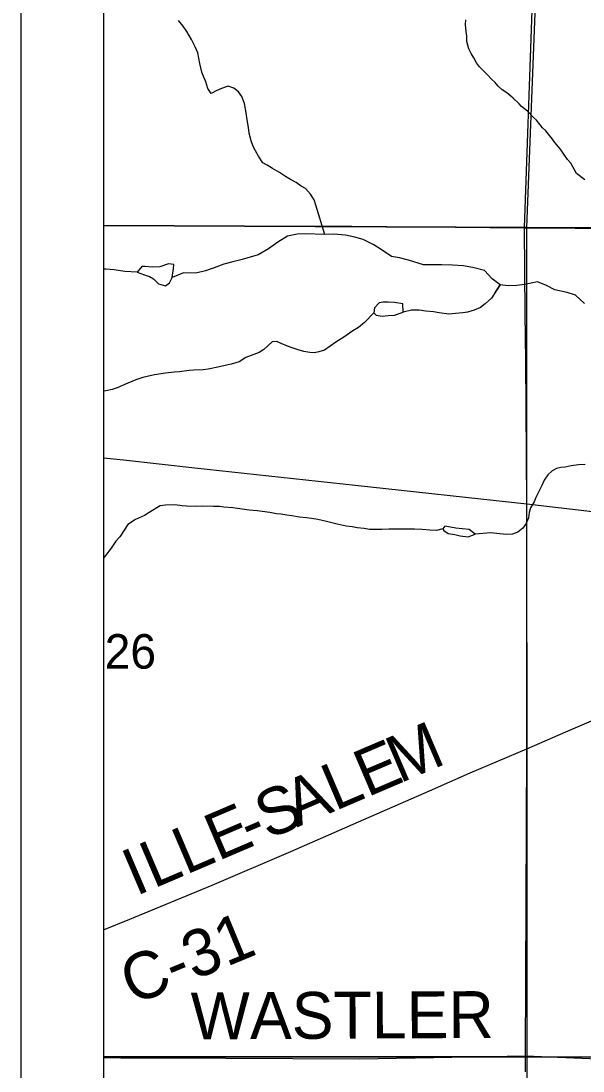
# Model space of a CAD drawing. Extents: x -209 to 4852, y 0 to 905.
# Drawn here: x 252.83 to 266.46, y 258.31 to 283.76 of the extents above; entities that cross this region are included whole.
import ezdxf

# ---------------------------------------------------------------- set-up
doc = ezdxf.new("R2010")
doc.units = 0
for name, color, linetype in [('Default', 7, 'Continuous'), ('GM_P_County_Alignment', 7, 'Continuous'), ('GM_X_County_Road', 7, 'Continuous'), ('GM_X_County_Road_Text', 7, 'Continuous'), ('GM_X_County_ROW', 7, 'Continuous'), ('GM_X_Major_River', 7, 'Continuous'), ('GM_X_Minor_Lake_Text', 7, 'Continuous'), ('GM_X_Minor_River', 7, 'Continuous'), ('GM_X_Rail_Line_Text', 7, 'Continuous'), ('GM_X_Township_Road', 7, 'Continuous'), ('GM_X_Township_Road_Text', 7, 'Continuous'), ('SH_Data', 7, 'Continuous')]:
    doc.layers.add(name, color=color, linetype=linetype)

msp = doc.modelspace()

# ---------------------------------------------------------------- linework, layer by layer
at = {"layer": 'Default'}
msp.add_lwpolyline([(390.832, 338.559), (254.832, 338.559), (254.832, 202.559), (390.832, 202.559)], close=True, dxfattribs=at)
at = {"layer": 'GM_X_County_Road'}
for points in [[(266.5, 279.912), (266.299, 280.069), (266.161, 280.315), (266.08, 280.408), (265.904, 280.663), (265.772, 280.818), (265.713, 280.903), (265.551, 281.104), (265.477, 281.174), (265.33, 281.36), (265.255, 281.423), (265.107, 281.578), (264.966, 281.695), (264.907, 281.758), (264.766, 281.898), (264.707, 281.945), (264.61, 282.023), (264.498, 282.094), (264.402, 282.187), (264.328, 282.273), (264.239, 282.358), (264.135, 282.467), (264.032, 282.568), (263.95, 282.654), (263.877, 282.754), (263.811, 282.87), (263.746, 282.978), (263.688, 283.093), (263.639, 283.269), (263.642, 283.398), (263.622, 283.512), (263.611, 283.679), (263.614, 283.793)], [(260.195, 278.593), (259.976, 279.298), (259.941, 279.428), (259.854, 279.567), (259.728, 279.706), (259.623, 279.762), (259.504, 279.849), (259.362, 279.92), (259.242, 279.992), (259.101, 280.094), (258.928, 280.189), (258.801, 280.268), (258.697, 280.331), (258.587, 280.486), (258.514, 280.617), (258.464, 280.724), (258.414, 280.862), (258.365, 281.046), (258.346, 281.183), (258.312, 281.373), (258.294, 281.541), (258.254, 281.769), (258.182, 281.931), (258.101, 282.046), (257.99, 282.14), (257.854, 282.189), (257.694, 282.132), (257.563, 282.075), (257.44, 282.01), (257.36, 282.125), (257.311, 282.294), (257.268, 282.401), (257.218, 282.524), (257.17, 282.737), (257.116, 282.997), (257.058, 283.142), (256.964, 283.319), (256.855, 283.512), (256.76, 283.643), (256.649, 283.775)], [(266.488, 276.919), (266.273, 277.123), (266.069, 277.183), (265.773, 277.245), (265.571, 277.35), (265.352, 277.44), (265.045, 277.381), (264.854, 277.356), (264.64, 277.348), (264.45, 277.369), (264.257, 277.519), (264.064, 277.715), (263.815, 277.783), (263.557, 277.829), (263.291, 277.845), (263.032, 277.853), (262.803, 277.852), (262.59, 277.858), (262.227, 277.968), (262.007, 278.021), (261.81, 278.057), (261.586, 278.208), (261.384, 278.336), (261.129, 278.465), (260.925, 278.525), (260.697, 278.57), (260.416, 278.594), (260.195, 278.593), (259.723, 278.607), (259.524, 278.598), (259.294, 278.551), (259.061, 278.406), (258.835, 278.246), (258.578, 278.094), (258.194, 277.984), (257.971, 277.93), (257.748, 277.868), (257.517, 277.784), (257.301, 277.707)], [(255.649, 277.674), (255.348, 277.697), (255.09, 277.736), (254.892, 277.749), (254.832, 277.749)], [(257.301, 277.707), (257.07, 277.653), (256.773, 277.662), (256.498, 277.55)], [(264.321, 277.166), (264.45, 277.369), (264.238, 277.045), (264.083, 276.912), (263.967, 276.824), (263.821, 276.752), (263.653, 276.71), (263.546, 276.69), (263.364, 276.672), (263.204, 276.661), (262.97, 276.689), (262.834, 276.715), (262.644, 276.728), (262.486, 276.754), (262.296, 276.759), (262.099, 276.707)], [(261.384, 276.692), (261.159, 276.46), (261.011, 276.335), (260.88, 276.255), (260.657, 276.101), (260.464, 275.977), (260.186, 275.786), (260.056, 275.744), (259.949, 275.724), (259.836, 275.726), (259.692, 275.753), (259.549, 275.794), (259.406, 275.843), (259.293, 275.884), (259.136, 275.949), (259.031, 275.997), (258.917, 275.992), (258.715, 275.8), (258.607, 275.726), (258.408, 275.655), (258.285, 275.605), (258.123, 275.503), (257.925, 275.447), (257.604, 275.371), (257.368, 275.324), (257.246, 275.312), (257.018, 275.302), (256.912, 275.29), (256.676, 275.265), (256.554, 275.253), (256.334, 275.228), (256.067, 275.189), (255.892, 275.148), (255.785, 275.12), (255.617, 275.071), (255.425, 274.985), (255.295, 274.927), (255.164, 274.877), (255.042, 274.835), (254.889, 274.801), (254.832, 274.789)], [(266.506, 273.012), (266.347, 273.008), (266.172, 272.982), (266.027, 272.948), (265.92, 272.943), (265.813, 272.915), (265.706, 272.865), (265.605, 272.761), (265.518, 272.634), (265.454, 272.506), (265.374, 272.341), (265.311, 272.214), (265.27, 272.109), (265.183, 271.967), (265.15, 271.853), (265.132, 271.725), (265.075, 271.582), (264.997, 271.47), (264.873, 271.375), (264.743, 271.325), (264.598, 271.321), (264.439, 271.332), (264.22, 271.36), (263.843, 271.327)], [(263.055, 271.458), (262.901, 271.415), (262.742, 271.427), (262.553, 271.439), (262.371, 271.451), (262.181, 271.448), (262.022, 271.445), (261.749, 271.444), (261.582, 271.44), (261.453, 271.443), (261.278, 271.44), (261.15, 271.466), (260.984, 271.478), (260.863, 271.504), (260.711, 271.522), (260.493, 271.566), (260.236, 271.633), (260.025, 271.684), (259.874, 271.702), (259.753, 271.721), (259.586, 271.74), (259.397, 271.767), (259.276, 271.785), (259.133, 271.812), (259.027, 271.822), (258.868, 271.849), (258.558, 271.894), (258.361, 271.907), (257.968, 271.962), (257.749, 271.982), (257.643, 271.993), (257.499, 271.996), (257.226, 272.003), (257.089, 271.999), (256.847, 272.005), (256.741, 272.015), (256.559, 272.034), (256.339, 272.032), (256.202, 272.013), (255.94, 271.852), (255.824, 271.779), (255.61, 271.678), (255.425, 271.561), (255.33, 271.427), (255.228, 271.263), (255.134, 271.159), (255.016, 270.987), (254.883, 270.808), (254.832, 270.743)]]:
    msp.add_lwpolyline(points, dxfattribs=at)
at = {"layer": 'GM_X_County_Road_Text'}
msp.add_lwpolyline([(254.832, 261.733), (255.474, 261.997), (257.469, 262.816), (259.373, 263.632), (261.011, 264.352), (262.733, 265.102), (263.722, 265.538), (265.097, 266.125), (266.037, 266.535), (267.494, 267.155), (269.358, 267.954), (271.025, 268.657), (272.15, 269.134)], dxfattribs=at)
at = {"layer": 'GM_X_County_ROW'}
for points in [[(265.066, 275.546), (265.056, 276.667), (265.038, 278.753), (265.221, 284.018), (265.504, 291.063)], [(254.832, 278.812), (256.416, 278.806), (258.293, 278.795), (260.849, 278.789), (265.038, 278.753), (274.866, 278.689), (276.171, 278.684)], [(265.098, 271.938), (265.098, 272.059), (265.066, 275.546)], [(265.098, 268.731), (265.098, 271.938)], [(265.06, 258.29), (265.059, 258.683), (265.097, 266.125), (265.098, 268.731)], [(254.832, 258.639), (255.254, 258.63), (257.798, 258.622), (261.048, 258.61), (265.059, 258.683), (265.259, 258.675)], [(265.259, 258.675), (267.988, 258.559), (268.192, 258.558), (270.752, 258.547), (273.918, 258.522), (276.318, 258.516), (278.671, 258.583), (281.933, 258.592), (284.632, 258.568), (286.663, 258.649)]]:
    msp.add_lwpolyline(points, dxfattribs=at)
at = {"layer": 'GM_X_Major_River'}
for points in [[(256.533, 277.762), (256.535, 277.86), (256.406, 277.878), (256.199, 277.807), (256.024, 277.795), (255.834, 277.815), (255.758, 277.816), (255.649, 277.674), (255.83, 277.61), (255.951, 277.569), (256.041, 277.514), (256.167, 277.397)], [(256.167, 277.397), (256.334, 277.348), (256.434, 277.422), (256.498, 277.55), (256.533, 277.762)], [(262.099, 276.707), (262.088, 276.912), (261.883, 276.939), (261.732, 276.95), (261.61, 276.953), (261.511, 276.932), (261.402, 276.813), (261.384, 276.692)], [(261.384, 276.692), (261.443, 276.637), (261.587, 276.611), (261.732, 276.623), (261.884, 276.635), (262.099, 276.707)], [(263.843, 271.327), (263.693, 271.437), (263.526, 271.455), (263.374, 271.474), (263.246, 271.499), (263.109, 271.518), (263.055, 271.458), (263.084, 271.412)], [(263.084, 271.412), (263.189, 271.341), (263.348, 271.322), (263.477, 271.282), (263.674, 271.262), (263.843, 271.327)]]:
    msp.add_lwpolyline(points, dxfattribs=at)
at = {"layer": 'GM_X_Minor_Lake_Text'}
msp.add_lwpolyline([(286.832, 338.559), (254.832, 338.559), (254.832, 238.66), (257.84, 238.598), (265.091, 238.636), (266.056, 238.553), (286.594, 238.536), (286.662, 258.396), (286.663, 258.649), (286.693, 269.675), (286.713, 277.524), (286.712, 278.679), (286.718, 281.051), (286.69, 288.656), (286.672, 293.142), (286.676, 298.975), (286.723, 309.11), (286.781, 319.004), (286.78, 319.227)], close=True, dxfattribs=at)
at = {"layer": 'GM_X_Minor_River'}
for points in [[(254.832, 298.938), (254.832, 278.807), (265.09, 278.757), (265.881, 298.954)], [(265.881, 298.954), (286.633, 298.983), (286.724, 278.709), (265.09, 278.757)], [(254.832, 278.807), (254.832, 258.659), (265.104, 258.659), (265.09, 278.757)], [(265.09, 278.757), (286.724, 278.709), (286.653, 258.613), (265.104, 258.659)], [(254.832, 258.659), (254.832, 238.664), (265.143, 238.636), (265.104, 258.659)], [(286.653, 258.613), (286.671, 258.401), (286.611, 238.471), (266.181, 238.644), (265.143, 238.636), (265.104, 258.659)]]:
    msp.add_lwpolyline(points, close=True, dxfattribs=at)
at = {"layer": 'GM_X_Rail_Line_Text'}
msp.add_lwpolyline([(254.832, 273.179), (255.321, 273.124), (257.047, 272.931), (260.936, 272.517), (265.098, 272.059), (266.959, 271.843), (268.601, 271.653), (270.697, 271.428), (273.026, 271.165), (275.381, 270.915), (278.956, 270.504), (280.037, 270.386), (280.393, 270.345)], dxfattribs=at)
at = {"layer": 'SH_Data'}
for p, q in [((252.832, 340.559), (252.832, 200.559)), ((254.832, 338.559), (254.832, 202.559))]:
    msp.add_line(p, q, dxfattribs=at)

# ---------------------------------------------------------------- texts
at = {"layer": 'GM_P_County_Alignment'}
for s, height, rotation, p in [('M', 1.136, 23.1327, (262.007, 265.278)), ('E', 1.136, 23.1353, (261.226, 264.944)), ('L', 1.136, 23.1383, (260.444, 264.61)), ('A', 1.136, 23.1321, (259.524, 264.217)), ('S', 1.136, 23.1382, (258.819, 263.916)), ('E', 1.136, 23.1353, (257.608, 263.398)), ('L', 1.136, 23.1383, (256.827, 263.064)), ('-', 1.136, 23.131, (258.39, 263.732)), ('I', 1.136, 23.135, (255.616, 262.547)), ('L', 1.136, 23.1325, (256.045, 262.73)), ('C-31', 1.1364, 22.4345, (255.547, 259.9))]:
    msp.add_text(s, height=height, rotation=rotation, dxfattribs=at).set_placement(p)
at = {"layer": 'GM_X_Township_Road'}
msp.add_text('WASTLER', height=1.1364, rotation=0.2882, dxfattribs=at).set_placement((256.949, 259.079))
at = {"layer": 'GM_X_Township_Road_Text'}
msp.add_text('26', height=0.8371, rotation=0, dxfattribs=at).set_placement((254.861, 268.066))

doc.saveas('drawing.dxf')
